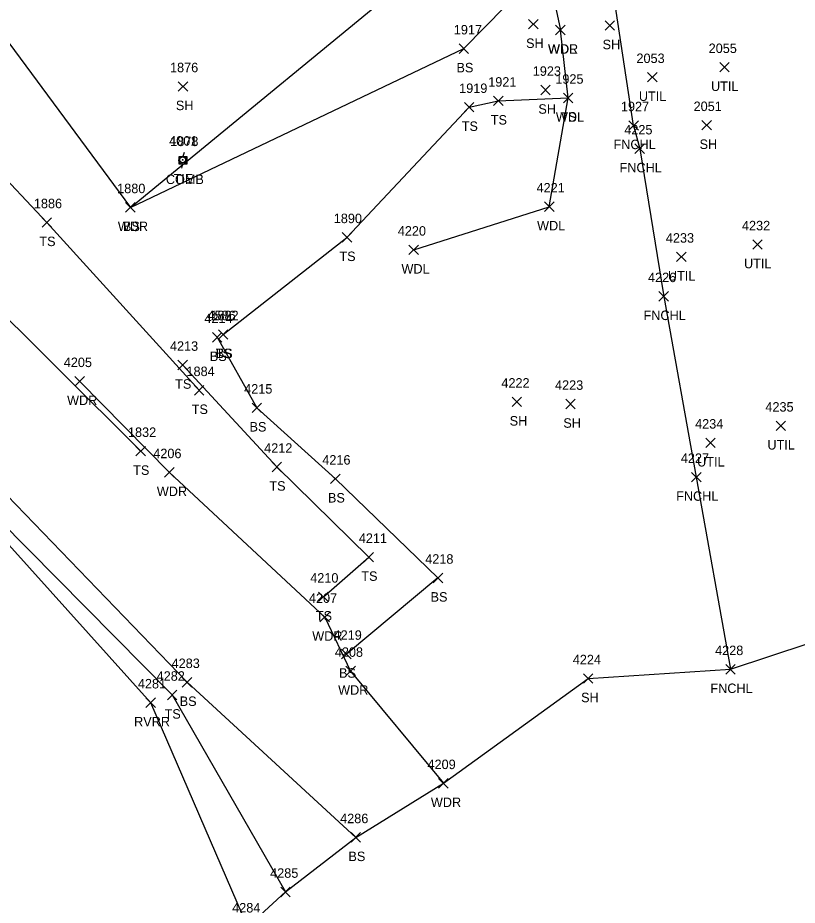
# Model space of a CAD drawing. Extents: x 1509053 to 1511576, y 400838 to 402572.
# Drawn here: x 1510484.5 to 1510649, y 401423.4 to 401610.6 of the extents above; entities that cross this region are included whole.
import ezdxf

# ---------------------------------------------------------------- set-up
doc = ezdxf.new("R2010")
doc.units = 0
for name, color, linetype in [('C_A', 7, 'Continuous'), ('C_I', 7, 'Continuous'), ('CBP', 7, 'Continuous'), ('L_A', 7, 'Continuous'), ('L_I', 7, 'Continuous'), ('L_TIC', 7, 'Continuous'), ('LAWA', 7, 'Continuous'), ('LAWE', 7, 'Continuous'), ('LELB', 7, 'Continuous'), ('LFNC', 7, 'Continuous'), ('LSOGP', 7, 'Continuous'), ('U_A', 7, 'Continuous'), ('U_I', 7, 'Continuous'), ('UDEFAULT', 7, 'Continuous'), ('UP', 7, 'Continuous')]:
    doc.layers.add(name, color=color, linetype=linetype)

msp = doc.modelspace()

# ---------------------------------------------------------------- linework, layer by layer
at = {"layer": 'CBP'}
for radius in [0.625, 0.0833]:
    msp.add_circle((1510519.34, 401580.63), radius, dxfattribs=at)
at = {"layer": 'L_TIC'}
for points in [[(1510592.33, 401608.23), (1510594.33, 401610.23)], [(1510594.33, 401608.23), (1510592.33, 401610.23)], [(1510608.47, 401607.97), (1510610.47, 401609.97)], [(1510610.47, 401607.97), (1510608.47, 401609.97)], [(1510598.04, 401607.01), (1510600.04, 401609.01)], [(1510600.04, 401607.01), (1510598.04, 401609.01)], [(1510598.04, 401607.01), (1510600.04, 401609.01)], [(1510600.04, 401607.01), (1510598.04, 401609.01)], [(1510577.68, 401603.08), (1510579.68, 401605.08)], [(1510579.68, 401603.08), (1510577.68, 401605.08)], [(1510518.42, 401595.11), (1510520.42, 401597.11)], [(1510520.42, 401595.11), (1510518.42, 401597.11)], [(1510594.91, 401594.36), (1510596.91, 401596.36)], [(1510596.91, 401594.36), (1510594.91, 401596.36)], [(1510584.95, 401592.06), (1510586.95, 401594.06)], [(1510586.95, 401592.06), (1510584.95, 401594.06)], [(1510599.68, 401592.68), (1510601.68, 401594.68)], [(1510601.68, 401592.68), (1510599.68, 401594.68)], [(1510599.68, 401592.68), (1510601.68, 401594.68)], [(1510601.68, 401592.68), (1510599.68, 401594.68)], [(1510578.82, 401590.73), (1510580.82, 401592.73)], [(1510580.82, 401590.73), (1510578.82, 401592.73)], [(1510613.51, 401586.88), (1510615.51, 401588.88)], [(1510615.51, 401586.88), (1510613.51, 401588.88)], [(1510628.93, 401586.92), (1510630.93, 401588.92)], [(1510630.93, 401586.92), (1510628.93, 401588.92)], [(1510614.79, 401581.98), (1510616.79, 401583.98)], [(1510616.79, 401581.98), (1510614.79, 401583.98)], [(1510507.3, 401569.59), (1510509.3, 401571.59)], [(1510509.3, 401569.59), (1510507.3, 401571.59)], [(1510507.3, 401569.59), (1510509.3, 401571.59)], [(1510509.3, 401569.59), (1510507.3, 401571.59)], [(1510595.71, 401569.74), (1510597.71, 401571.74)], [(1510597.71, 401569.74), (1510595.71, 401571.74)], [(1510489.69, 401566.42), (1510491.69, 401568.42)], [(1510491.69, 401566.42), (1510489.69, 401568.42)], [(1510553.01, 401563.27), (1510555.01, 401565.27)], [(1510555.01, 401563.27), (1510553.01, 401565.27)], [(1510567.09, 401560.63), (1510569.09, 401562.63)], [(1510569.09, 401560.63), (1510567.09, 401562.63)], [(1510619.85, 401550.82), (1510621.85, 401552.82)], [(1510621.85, 401550.82), (1510619.85, 401552.82)], [(1510526.89, 401542.79), (1510528.89, 401544.79)], [(1510528.89, 401542.79), (1510526.89, 401544.79)], [(1510526.89, 401542.79), (1510528.89, 401544.79)], [(1510528.89, 401542.79), (1510526.89, 401544.79)], [(1510525.62, 401542.18), (1510527.62, 401544.18)], [(1510527.62, 401542.18), (1510525.62, 401544.18)], [(1510518.35, 401536.33), (1510520.35, 401538.33)], [(1510520.35, 401536.33), (1510518.35, 401538.33)], [(1510496.59, 401532.9), (1510498.59, 401534.9)], [(1510498.59, 401532.9), (1510496.59, 401534.9)], [(1510521.84, 401531), (1510523.84, 401533)], [(1510523.84, 401531), (1510521.84, 401533)], [(1510588.86, 401528.56), (1510590.86, 401530.56)], [(1510590.86, 401528.56), (1510588.86, 401530.56)], [(1510600.18, 401528.1), (1510602.18, 401530.1)], [(1510602.18, 401528.1), (1510600.18, 401530.1)], [(1510534.01, 401527.3), (1510536.01, 401529.3)], [(1510536.01, 401527.3), (1510534.01, 401529.3)], [(1510509.49, 401518.16), (1510511.49, 401520.16)], [(1510511.49, 401518.16), (1510509.49, 401520.16)], [(1510538.23, 401514.82), (1510540.23, 401516.82)], [(1510540.23, 401514.82), (1510538.23, 401516.82)], [(1510515.53, 401513.68), (1510517.53, 401515.68)], [(1510517.53, 401513.68), (1510515.53, 401515.68)], [(1510626.73, 401512.69), (1510628.73, 401514.69)], [(1510628.73, 401512.69), (1510626.73, 401514.69)], [(1510550.56, 401512.32), (1510552.56, 401514.32)], [(1510552.56, 401512.32), (1510550.56, 401514.32)], [(1510557.63, 401495.8), (1510559.63, 401497.8)], [(1510559.63, 401495.8), (1510557.63, 401497.8)], [(1510572.22, 401491.41), (1510574.22, 401493.41)], [(1510574.22, 401491.41), (1510572.22, 401493.41)], [(1510548.04, 401487.42), (1510550.04, 401489.42)], [(1510550.04, 401487.42), (1510548.04, 401489.42)], [(1510548.32, 401483.15), (1510550.32, 401485.15)], [(1510550.32, 401483.15), (1510548.32, 401485.15)], [(1510552.89, 401475.36), (1510554.89, 401477.36)], [(1510554.89, 401475.36), (1510552.89, 401477.36)], [(1510553.79, 401471.77), (1510555.79, 401473.77)], [(1510555.79, 401471.77), (1510553.79, 401473.77)], [(1510633.96, 401472.13), (1510635.96, 401474.13)], [(1510635.96, 401472.13), (1510633.96, 401474.13)], [(1510519.27, 401469.4), (1510521.27, 401471.4)], [(1510521.27, 401469.4), (1510519.27, 401471.4)], [(1510603.93, 401470.19), (1510605.93, 401472.19)], [(1510605.93, 401470.19), (1510603.93, 401472.19)], [(1510516.11, 401466.72), (1510518.11, 401468.72)], [(1510518.11, 401466.72), (1510516.11, 401468.72)], [(1510511.58, 401465.1), (1510513.58, 401467.1)], [(1510513.58, 401465.1), (1510511.58, 401467.1)], [(1510573.36, 401448.08), (1510575.36, 401450.08)], [(1510575.36, 401448.08), (1510573.36, 401450.08)], [(1510554.88, 401436.67), (1510556.88, 401438.67)], [(1510556.88, 401436.67), (1510554.88, 401438.67)], [(1510540.06, 401425.15), (1510542.06, 401427.15)], [(1510542.06, 401425.15), (1510540.06, 401427.15)]]:
    msp.add_lwpolyline(points, dxfattribs=at)
at = {"layer": 'LAWA'}
for points in [[(1510429.51, 401625.06), (1510438.15, 401625.45), (1510460.38, 401618.46), (1510476.79, 401613.15), (1510508.3, 401570.59), (1510574.11, 401624.66), (1510596.09, 401621.92), (1510599.04, 401608.01)], [(1510600.68, 401593.68), (1510599.04, 401608.01)], [(1510596.71, 401570.74), (1510600.68, 401593.68)], [(1510568.09, 401561.63), (1510596.71, 401570.74)], [(1510497.59, 401533.9), (1510516.53, 401514.68), (1510549.32, 401484.15), (1510554.79, 401472.77), (1510574.36, 401449.08)]]:
    msp.add_lwpolyline(points, dxfattribs=at)
at = {"layer": 'LAWE'}
msp.add_lwpolyline([(1510473.88, 401509.07), (1510512.58, 401466.1), (1510533.05, 401418.83)], dxfattribs=at)
at = {"layer": 'LELB'}
for points in [[(1510508.3, 401570.59), (1510578.68, 401604.08), (1510596.09, 401621.92)], [(1510527.89, 401543.79), (1510554.01, 401564.27), (1510579.82, 401591.73), (1510585.95, 401593.06), (1510600.68, 401593.68)], [(1510522.84, 401532), (1510490.69, 401567.42), (1510466.83, 401592.69)], [(1510452.68, 401575.84), (1510475.46, 401553.98), (1510510.5, 401519.16)], [(1510526.62, 401543.18), (1510535.01, 401528.3), (1510551.56, 401513.32), (1510573.22, 401492.41), (1510553.89, 401476.36)], [(1510549.04, 401488.42), (1510558.63, 401496.8), (1510539.23, 401515.82), (1510519.35, 401537.33)], [(1510478.43, 401513.71), (1510520.27, 401470.4), (1510555.88, 401437.67)], [(1510474.54, 401510.7), (1510517.11, 401467.72), (1510541.06, 401426.15)]]:
    msp.add_lwpolyline(points, dxfattribs=at)
at = {"layer": 'LFNC'}
for points in [[(1510614.51, 401587.89), (1510608.95, 401624.6), (1510623.43, 401626.88), (1510653.12, 401627.01), (1510659.85, 401628.01), (1510675.67, 401629.95), (1510724.73, 401633.47), (1510773.82, 401637.15), (1510823.89, 401641.02), (1510977.71, 401652.22)], [(1510614.51, 401587.89), (1510615.79, 401582.98)], [(1510615.79, 401582.98), (1510620.85, 401551.82), (1510627.73, 401513.69), (1510634.96, 401473.13)]]:
    msp.add_lwpolyline(points, dxfattribs=at)
at = {"layer": 'LSOGP'}
msp.add_lwpolyline([(1510344.01, 401396.04), (1510358.53, 401426.13), (1510361.96, 401428.29), (1510375.28, 401447.94), (1510395.91, 401466.66), (1510416.71, 401491.56), (1510431.72, 401516.61), (1510444.48, 401539.03), (1510473.88, 401509.07), (1510512.58, 401466.1), (1510533.05, 401418.83), (1510541.06, 401426.15), (1510555.88, 401437.67), (1510574.36, 401449.08), (1510604.93, 401471.19), (1510634.96, 401473.13), (1510676.42, 401486.89)], dxfattribs=at)
at = {"layer": 'UDEFAULT'}
for points in [[(1510632.67, 401599.16), (1510634.67, 401601.16)], [(1510634.67, 401599.16), (1510632.67, 401601.16)], [(1510617.44, 401597.05), (1510619.44, 401599.05)], [(1510619.44, 401597.05), (1510617.44, 401599.05)], [(1510639.63, 401561.75), (1510641.63, 401563.75)], [(1510641.63, 401561.75), (1510639.63, 401563.75)], [(1510623.57, 401559.15), (1510625.57, 401561.15)], [(1510625.57, 401559.15), (1510623.57, 401561.15)], [(1510644.57, 401523.5), (1510646.57, 401525.5)], [(1510646.57, 401523.5), (1510644.57, 401525.5)], [(1510629.74, 401519.92), (1510631.74, 401521.92)], [(1510631.74, 401519.92), (1510629.74, 401521.92)]]:
    msp.add_lwpolyline(points, dxfattribs=at)
at = {"layer": 'UP'}
for p, q in [((1510519.65, 401582.19), (1510519.4, 401581.36)), ((1510518.57, 401579.69), (1510518.57, 401581.36)), ((1510518.57, 401581.36), (1510520.23, 401581.36)), ((1510519.4, 401580.52), (1510519.4, 401580.52)), ((1510520.23, 401581.36), (1510520.23, 401579.69)), ((1510520.23, 401579.69), (1510518.57, 401579.69)), ((1510519.15, 401578.86), (1510519.4, 401579.69))]:
    msp.add_line(p, q, dxfattribs=at)
msp.add_circle((1510519.4, 401580.52), 0.833, dxfattribs=at)

# ---------------------------------------------------------------- texts
at = {"layer": 'C_A'}
msp.add_text('TIE', height=2, dxfattribs=at).set_placement((1510517.42, 401575.63))
at = {"layer": 'C_I'}
msp.add_text('4001', height=2, dxfattribs=at).set_placement((1510516.49, 401583.63))
at = {"layer": 'L_A'}
for s, p in [('SH', (1510591.81, 401604.23)), ('WDR', (1510596.41, 401603.01)), ('WDL', (1510596.46, 401603.01)), ('SH', (1510607.96, 401603.97)), ('BS', (1510577.12, 401599.08)), ('SH', (1510517.91, 401591.11)), ('SH', (1510594.4, 401590.35)), ('TS', (1510584.36, 401588.06)), ('WDL', (1510598.09, 401588.68)), ('TS', (1510599.08, 401588.68)), ('TS', (1510578.23, 401586.73)), ('FNCHL', (1510610.26, 401582.88)), ('SH', (1510628.42, 401582.92)), ('FNCHL', (1510611.54, 401577.98)), ('WDR', (1510505.66, 401565.59)), ('BS', (1510506.74, 401565.59)), ('WDL', (1510594.13, 401565.74)), ('TS', (1510489.1, 401562.42)), ('TS', (1510552.42, 401559.27)), ('WDL', (1510565.51, 401556.63)), ('FNCHL', (1510616.6, 401546.82)), ('TS', (1510526.3, 401538.79)), ('BS', (1510526.33, 401538.79)), ('BS', (1510525.06, 401538.18)), ('TS', (1510517.76, 401532.33)), ('WDR', (1510494.95, 401528.9)), ('TS', (1510521.25, 401527)), ('SH', (1510588.35, 401524.56)), ('SH', (1510599.67, 401524.1)), ('BS', (1510533.45, 401523.3)), ('TS', (1510508.9, 401514.16)), ('TS', (1510537.64, 401510.82)), ('WDR', (1510513.89, 401509.68)), ('FNCHL', (1510623.48, 401508.69)), ('BS', (1510550, 401508.32)), ('TS', (1510557.04, 401491.8)), ('BS', (1510571.66, 401487.41)), ('TS', (1510547.45, 401483.42)), ('WDR', (1510546.68, 401479.15)), ('BS', (1510552.33, 401471.36)), ('WDR', (1510552.15, 401467.77)), ('FNCHL', (1510630.71, 401468.13)), ('SH', (1510603.42, 401466.19)), ('BS', (1510518.71, 401465.4)), ('TS', (1510515.52, 401462.72)), ('RVRR', (1510509.09, 401461.1)), ('WDR', (1510571.72, 401444.08)), ('BS', (1510554.32, 401432.67))]:
    msp.add_text(s, height=2, dxfattribs=at).set_placement(p)
at = {"layer": 'L_I'}
for s, p in [('1917', (1510576.56, 401607.08)), ('1876', (1510516.67, 401599.11)), ('1923', (1510593.22, 401598.35)), ('1925', (1510597.98, 401596.68)), ('1925', (1510597.98, 401596.68)), ('1921', (1510583.82, 401596.06)), ('1919', (1510577.69, 401594.73)), ('1927', (1510611.82, 401590.88)), ('2051', (1510627.16, 401590.92)), ('4225', (1510612.53, 401585.98)), ('1880', (1510505.52, 401573.59)), ('1880', (1510505.52, 401573.59)), ('4221', (1510594.02, 401573.74)), ('1886', (1510487.94, 401570.42)), ('1890', (1510551.23, 401567.27)), ('4220', (1510564.74, 401564.63)), ('4226', (1510617.54, 401554.82)), ('4214', (1510523.93, 401546.18)), ('4586', (1510524.58, 401546.79)), ('1882', (1510525.2, 401546.79)), ('4213', (1510516.66, 401540.33)), ('4205', (1510494.25, 401536.9)), ('1884', (1510520.15, 401535)), ('4215', (1510532.32, 401531.3)), ('4222', (1510586.6, 401532.56)), ('4223', (1510597.92, 401532.1)), ('1832', (1510507.8, 401522.16)), ('4212', (1510536.54, 401518.82)), ('4206', (1510513.14, 401517.68)), ('4216', (1510548.81, 401516.32)), ('4227', (1510624.47, 401516.69)), ('4211', (1510556.51, 401499.8)), ('4218', (1510570.53, 401495.41)), ('4210', (1510546.26, 401491.42)), ('4207', (1510545.98, 401487.15)), ('4219', (1510551.19, 401479.36)), ('4208', (1510551.45, 401475.77)), ('4228', (1510631.7, 401476.13)), ('4283', (1510517.01, 401473.4)), ('4224', (1510601.67, 401474.19)), ('4282', (1510513.85, 401470.72)), ('4281', (1510509.89, 401469.1)), ('4209', (1510571.01, 401452.08)), ('4286', (1510552.57, 401440.67)), ('4285', (1510537.8, 401429.15)), ('4284', (1510529.79, 401421.83))]:
    msp.add_text(s, height=2, dxfattribs=at).set_placement(p)
at = {"layer": 'U_A'}
for s, p in [('UTIL', (1510630.84, 401595.16)), ('UTIL', (1510615.61, 401593.05)), ('COMB', (1510515.79, 401575.52)), ('UTIL', (1510637.8, 401557.75)), ('UTIL', (1510621.74, 401555.15)), ('UTIL', (1510642.74, 401519.5)), ('UTIL', (1510627.91, 401515.92))]:
    msp.add_text(s, height=2, dxfattribs=at).set_placement(p)
at = {"layer": 'U_I'}
for s, p in [('2055', (1510630.34, 401603.16)), ('2053', (1510615.1, 401601.05)), ('1878', (1510516.71, 401583.52)), ('4232', (1510637.37, 401565.75)), ('4233', (1510621.31, 401563.15)), ('4235', (1510642.31, 401527.5)), ('4234', (1510627.48, 401523.92))]:
    msp.add_text(s, height=2, dxfattribs=at).set_placement(p)

doc.saveas('drawing.dxf')
